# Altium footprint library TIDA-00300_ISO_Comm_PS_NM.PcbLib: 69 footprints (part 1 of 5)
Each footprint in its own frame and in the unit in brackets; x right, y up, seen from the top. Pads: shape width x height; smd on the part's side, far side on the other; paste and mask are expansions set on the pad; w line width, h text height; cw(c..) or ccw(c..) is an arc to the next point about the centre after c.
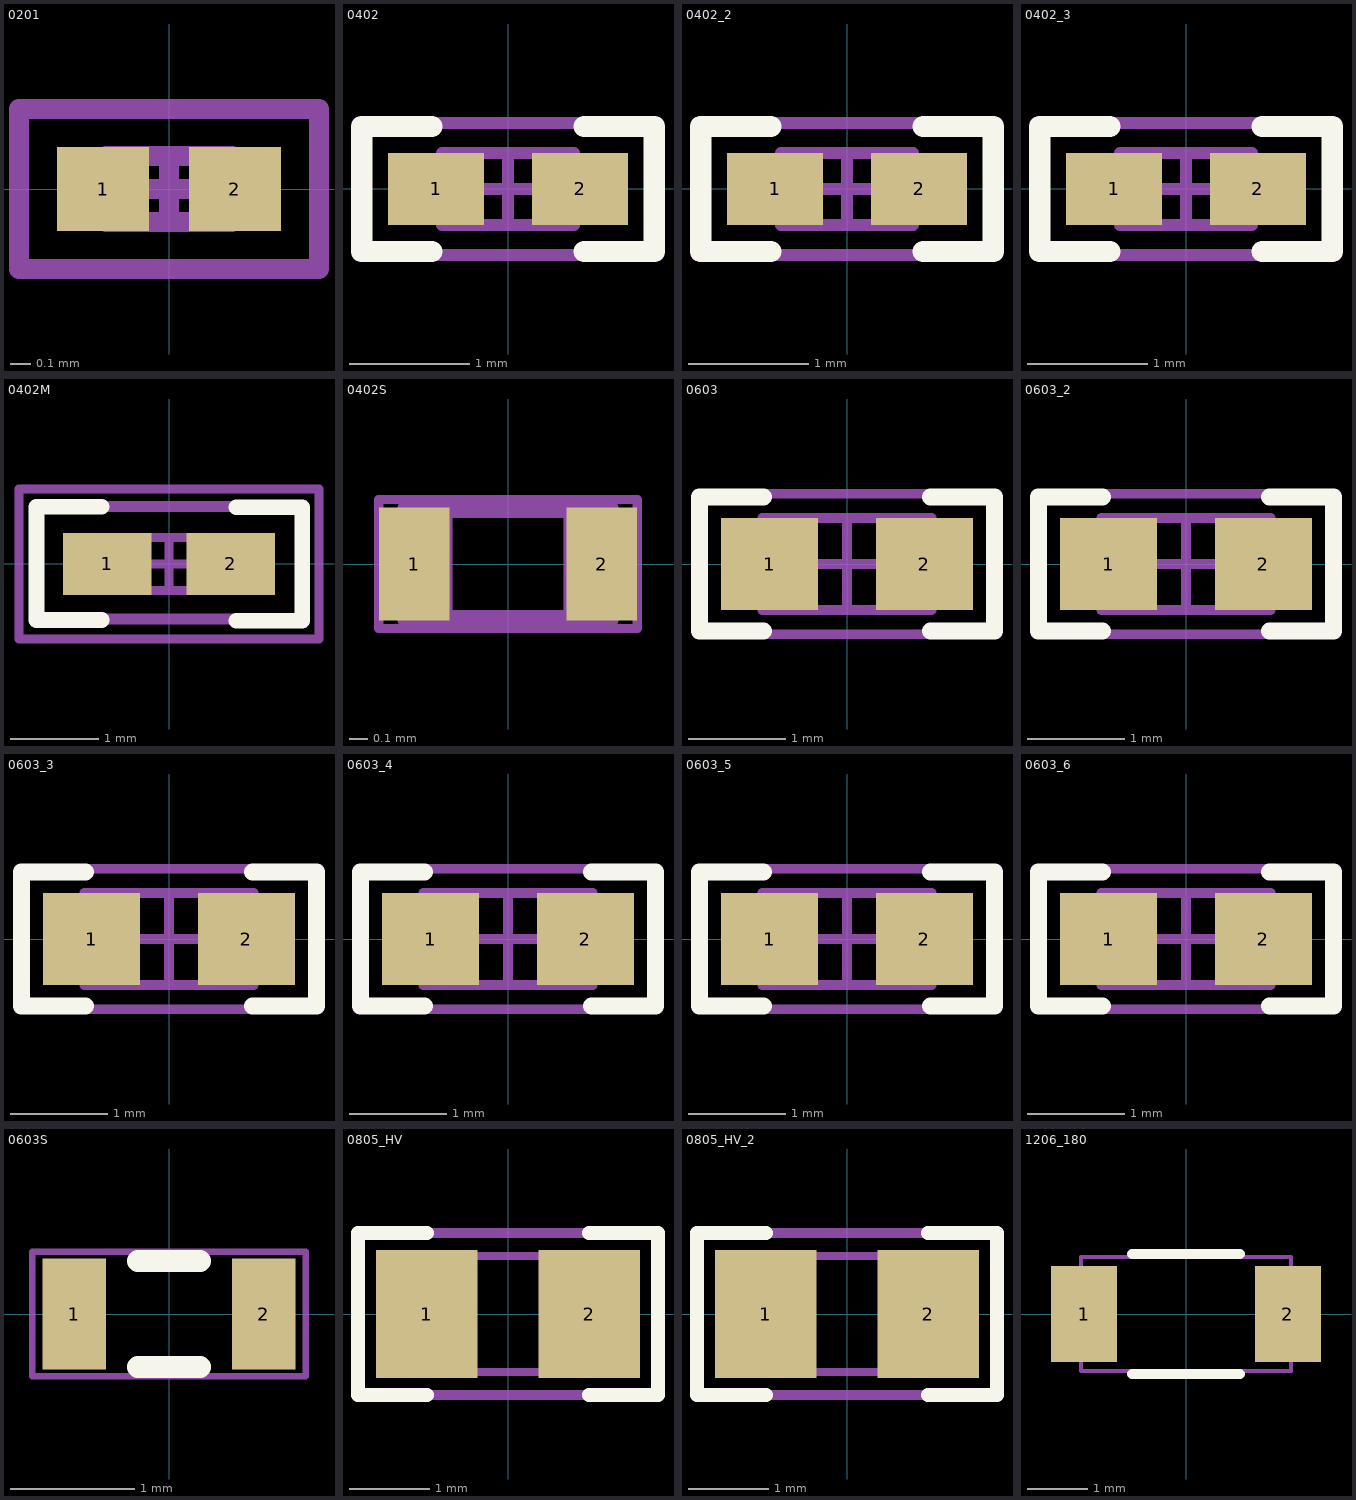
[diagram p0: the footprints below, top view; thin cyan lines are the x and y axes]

## 0201 [mm] "Data from Kemet datasheet CC101_COM dated 7/28/11"
height 0.26
pads (2):
  rect 0.46x0.42 smd mask+0.048: 1(-0.33,0) 2(0.33,0)
Mechanical 5:
  lines w0.1: -0.75,-0.4 0.75,-0.4 0.75,0.4 -0.75,0.4 -0.75,-0.4
  text ".Designator" at -0.654,-1.067 h0.51
Mechanical 13:
  lines w0.1: -0.215,-0.165 -0.215,0.165 ; 0.215,-0.165 0.215,0.165 ; -0.315,-0.165 -0.315,0.165 0.315,0.165 0.315,-0.165 -0.315,-0.165
Mechanical 15:
  lines w0.1: -0.165,0 0.165,0 ; 0,-0.165 0,0.165 ; -0.75,-0.4 -0.75,0.4 0.75,0.4 0.75,-0.4 -0.75,-0.4
3D body: height 0.26, standoff 0, extent -0.314,-0.164 -0.216,0.164
3D body: height 0.26, standoff 0, extent -0.214,-0.164 0.214,0.164
3D body: height 0.26, standoff 0, extent 0.216,-0.164 0.314,0.164

## 0402 [mm] "0402 from SM-752 data"
height 0.6
pads (2):
  rect 0.8x0.6 smd: 1(-0.6,0) 2(0.6,0)
Top Overlay:
  lines w0.178: -0.635,-0.521 -1.219,-0.521 -1.219,0.521 -0.635,0.521 ; 0.635,-0.521 1.219,-0.521 1.219,0.521 0.635,0.521
Mechanical 5:
  lines w0.1: -1.25,-0.55 1.25,-0.55 1.25,0.55 -1.25,0.55 -1.25,-0.55
  text ".Designator" at 0.675,0.165 h0.51
Mechanical 13:
  lines w0.1: -0.35,-0.3 -0.35,0.3 ; 0.35,-0.3 0.35,0.3 ; -0.55,-0.3 -0.55,0.3 0.55,0.3 0.55,-0.3 -0.55,-0.3
Mechanical 15:
  lines w0.1: -0.3,0 0.3,0 ; 0,-0.3 0,0.3 ; -1.25,-0.55 -1.25,0.55 1.25,0.55 1.25,-0.55 -1.25,-0.55
3D body: height 0.6, standoff 0, extent -0.549,-0.299 -0.351,0.299
3D body: height 0.6, standoff 0, extent -0.349,-0.299 0.349,0.299
3D body: height 0.6, standoff 0, extent 0.351,-0.299 0.549,0.299

## 0402_2 [mm]
pads (2):
  rect 0.8x0.6 smd: 1(-0.6,0) 2(0.6,0)
Top Overlay:
  lines w0.178: -0.635,-0.521 -1.219,-0.521 -1.219,0.521 -0.635,0.521 ; 0.635,-0.521 1.219,-0.521 1.219,0.521 0.635,0.521
Mechanical 5:
  lines w0.1: -1.25,-0.55 1.25,-0.55 1.25,0.55 -1.25,0.55 -1.25,-0.55
  text ".Designator" at 0.848,0.205 h0.51
Mechanical 13:
  lines w0.1: -0.35,-0.3 -0.35,0.3 ; 0.35,-0.3 0.35,0.3 ; -0.55,-0.3 -0.55,0.3 0.55,0.3 0.55,-0.3 -0.55,-0.3
Mechanical 15:
  lines w0.1: -0.3,0 0.3,0 ; 0,-0.3 0,0.3 ; -1.25,-0.55 -1.25,0.55 1.25,0.55 1.25,-0.55 -1.25,-0.55
3D body: height 0.6, standoff 0, extent -0.549,-0.299 -0.351,0.299
3D body: height 0.6, standoff 0, extent -0.349,-0.299 0.349,0.299
3D body: height 0.6, standoff 0, extent 0.351,-0.299 0.549,0.299

## 0402_3 [mm]
pads (2):
  rect 0.8x0.6 smd: 1(-0.6,0) 2(0.6,0)
Top Overlay:
  lines w0.178: -0.635,-0.521 -1.219,-0.521 -1.219,0.521 -0.635,0.521 ; 0.635,-0.521 1.219,-0.521 1.219,0.521 0.635,0.521
Mechanical 5:
  lines w0.1: -1.25,-0.55 1.25,-0.55 1.25,0.55 -1.25,0.55 -1.25,-0.55
  text ".Designator" at 0.533,0.278 h0.51
Mechanical 13:
  lines w0.1: -0.35,-0.3 -0.35,0.3 ; 0.35,-0.3 0.35,0.3 ; -0.55,-0.3 -0.55,0.3 0.55,0.3 0.55,-0.3 -0.55,-0.3
Mechanical 15:
  lines w0.1: -0.3,0 0.3,0 ; 0,-0.3 0,0.3 ; -1.25,-0.55 -1.25,0.55 1.25,0.55 1.25,-0.55 -1.25,-0.55
3D body: height 0.6, standoff 0, extent -0.549,-0.299 -0.351,0.299
3D body: height 0.6, standoff 0, extent -0.349,-0.299 0.349,0.299
3D body: height 0.6, standoff 0, extent 0.351,-0.299 0.549,0.299

## 0402M [mm] "0402 from SM-752 data"
height 0.6
pads (2):
  rect 1x0.7 smd: 1(-0.7,0) 2(0.7,0)
Top Overlay:
  lines w0.178: -1.501,-0.635 -0.762,-0.635 ; -1.501,-0.627 -1.501,0.63 ; -1.501,0.65 -0.762,0.65 ; 0.762,-0.643 1.511,-0.643 ; 0.762,0.643 1.511,0.643 ; 1.511,-0.622 1.511,0.635
Mechanical 5:
  lines w0.127: -1.5,-0.625 -1.5,0.65 1.525,0.65 1.525,-0.625 -1.5,-0.625
  text ".Designator" at -1.303,-0.355 h0.51
Mechanical 13:
  lines w0.1: -0.35,-0.3 -0.35,0.3 ; 0.35,-0.3 0.35,0.3 ; -0.55,-0.3 -0.55,0.3 0.55,0.3 0.55,-0.3 -0.55,-0.3
Mechanical 15:
  lines w0.1: -0.3,0 0.3,0 ; 0,-0.3 0,0.3 ; -1.7,-0.85 -1.7,0.85 1.7,0.85 1.7,-0.85 -1.7,-0.85
3D body: height 0.6, standoff 0, extent -0.549,-0.299 -0.351,0.299
3D body: height 0.6, standoff 0, extent -0.349,-0.299 0.349,0.299
3D body: height 0.6, standoff 0, extent 0.351,-0.299 0.549,0.299

## 0402S [mil] "Based on C0402S footprint from PADS legacy"
height 23.62
pads (2):
  rect 15x24 smd: 1(-20,0) 2(20,0)
Mechanical 5:
  lines w1.97: -27.56,-13.78 27.56,-13.78 27.56,13.78 -27.56,13.78 -27.56,-13.78
  text ".Designator" at 26.06,-22 h20
Mechanical 13:
  lines w3.94: -13.78,-11.81 -13.78,11.81 ; 13.78,-11.81 13.78,11.81 ; -21.65,-11.81 -21.65,11.81 21.65,11.81 21.65,-11.81 -21.65,-11.81
3D body: height 23.62, standoff 0, extent -21.63,-11.79 -13.8,11.79
3D body: height 23.62, standoff 0, extent -13.76,-11.79 13.76,11.79
3D body: height 23.62, standoff 0, extent 13.8,-11.79 21.63,11.79

## 0603 [mm] "0603 from SM-752 data"
height 1
pads (2):
  rect 1x0.95 smd: 1(-0.8,0) 2(0.8,0)
Top Overlay:
  lines w0.178: -0.864,-0.691 -1.524,-0.691 -1.524,0.693 -0.864,0.693 ; 0.864,-0.691 1.524,-0.691 1.524,0.693 0.864,0.693
Mechanical 5:
  lines w0.1: -1.55,-0.725 1.55,-0.725 1.55,0.725 -1.55,0.725 -1.55,-0.725
  text ".Designator" at 0.961,0.216 h0.51
Mechanical 13:
  lines w0.1: -0.55,-0.475 -0.55,0.475 ; 0.55,-0.475 0.55,0.475 ; -0.875,-0.475 -0.875,0.475 0.875,0.475 0.875,-0.475 -0.875,-0.475
Mechanical 15:
  lines w0.1: -0.475,0 0.475,0 ; 0,-0.475 0,0.475 ; -1.55,-0.725 -1.55,0.725 1.55,0.725 1.55,-0.725 -1.55,-0.725
3D body: height 1, standoff 0, extent 0.551,-0.474 0.874,0.474
3D body: height 1, standoff 0, extent -0.549,-0.474 0.549,0.474
3D body: height 1, standoff 0, extent -0.874,-0.474 -0.551,0.474

## 0603_2 [mm]
pads (2):
  rect 1x0.95 smd: 1(-0.8,0) 2(0.8,0)
Top Overlay:
  lines w0.178: -0.864,-0.691 -1.524,-0.691 -1.524,0.693 -0.864,0.693 ; 0.864,-0.691 1.524,-0.691 1.524,0.693 0.864,0.693
Mechanical 5:
  lines w0.1: -1.55,-0.725 1.55,-0.725 1.55,0.725 -1.55,0.725 -1.55,-0.725
  text ".Designator" at -0.802,-0.224 h0.51
Mechanical 13:
  lines w0.1: -0.55,-0.475 -0.55,0.475 ; 0.55,-0.475 0.55,0.475 ; -0.875,-0.475 -0.875,0.475 0.875,0.475 0.875,-0.475 -0.875,-0.475
Mechanical 15:
  lines w0.1: -0.475,0 0.475,0 ; 0,-0.475 0,0.475 ; -1.55,-0.725 -1.55,0.725 1.55,0.725 1.55,-0.725 -1.55,-0.725
3D body: height 1, standoff 0, extent 0.551,-0.474 0.874,0.474
3D body: height 1, standoff 0, extent -0.549,-0.474 0.549,0.474
3D body: height 1, standoff 0, extent -0.874,-0.474 -0.551,0.474

## 0603_3 [mm]
pads (2):
  rect 1x0.95 smd: 1(-0.8,0) 2(0.8,0)
Top Overlay:
  lines w0.178: -0.864,-0.691 -1.524,-0.691 -1.524,0.693 -0.864,0.693 ; 0.864,-0.691 1.524,-0.691 1.524,0.693 0.864,0.693
Mechanical 5:
  lines w0.1: -1.55,-0.725 1.55,-0.725 1.55,0.725 -1.55,0.725 -1.55,-0.725
  text ".Designator" at -0.859,-0.239 h0.51
Mechanical 13:
  lines w0.1: -0.55,-0.475 -0.55,0.475 ; 0.55,-0.475 0.55,0.475 ; -0.875,-0.475 -0.875,0.475 0.875,0.475 0.875,-0.475 -0.875,-0.475
Mechanical 15:
  lines w0.1: -0.475,0 0.475,0 ; 0,-0.475 0,0.475 ; -1.55,-0.725 -1.55,0.725 1.55,0.725 1.55,-0.725 -1.55,-0.725
3D body: height 1, standoff 0, extent 0.551,-0.474 0.874,0.474
3D body: height 1, standoff 0, extent -0.549,-0.474 0.549,0.474
3D body: height 1, standoff 0, extent -0.874,-0.474 -0.551,0.474

## 0603_4 [mm]
pads (2):
  rect 1x0.95 smd: 1(-0.8,0) 2(0.8,0)
Top Overlay:
  lines w0.178: -0.864,-0.691 -1.524,-0.691 -1.524,0.693 -0.864,0.693 ; 0.864,-0.691 1.524,-0.691 1.524,0.693 0.864,0.693
Mechanical 5:
  lines w0.1: -1.55,-0.725 -1.55,0.725 1.55,0.725 1.55,-0.725 -1.55,-0.725
  text ".Designator" at 0.94,0.254 h0.51
Mechanical 13:
  lines w0.1: -0.55,-0.475 -0.55,0.475 ; 0.55,-0.475 0.55,0.475 ; -0.875,-0.475 0.875,-0.475 0.875,0.475 -0.875,0.475 -0.875,-0.475
Mechanical 15:
  lines w0.1: -0.475,0 0.475,0 ; 0,-0.475 0,0.475 ; -1.55,-0.725 1.55,-0.725 1.55,0.725 -1.55,0.725 -1.55,-0.725
3D body: height 1, standoff 0, extent -0.874,-0.474 -0.551,0.474
3D body: height 1, standoff 0, extent -0.549,-0.474 0.549,0.474
3D body: height 1, standoff 0, extent 0.551,-0.474 0.874,0.474

## 0603_5 [mm]
pads (2):
  rect 1x0.95 smd: 1(-0.8,0) 2(0.8,0)
Top Overlay:
  lines w0.178: -0.864,-0.691 -1.524,-0.691 -1.524,0.693 -0.864,0.693 ; 0.864,-0.691 1.524,-0.691 1.524,0.693 0.864,0.693
Mechanical 5:
  lines w0.1: -1.55,-0.725 1.55,-0.725 1.55,0.725 -1.55,0.725 -1.55,-0.725
  text ".Designator" at 0.533,0.254 h0.51
Mechanical 13:
  lines w0.1: -0.55,-0.475 -0.55,0.475 ; 0.55,-0.475 0.55,0.475 ; -0.875,-0.475 -0.875,0.475 0.875,0.475 0.875,-0.475 -0.875,-0.475
Mechanical 15:
  lines w0.1: -0.475,0 0.475,0 ; 0,-0.475 0,0.475 ; -1.55,-0.725 -1.55,0.725 1.55,0.725 1.55,-0.725 -1.55,-0.725
3D body: height 1, standoff 0, extent 0.551,-0.474 0.874,0.474
3D body: height 1, standoff 0, extent -0.549,-0.474 0.549,0.474
3D body: height 1, standoff 0, extent -0.874,-0.474 -0.551,0.474

## 0603_6 [mm]
pads (2):
  rect 1x0.95 smd: 1(-0.8,0) 2(0.8,0)
Top Overlay:
  lines w0.178: -0.864,-0.691 -1.524,-0.691 -1.524,0.693 -0.864,0.693 ; 0.864,-0.691 1.524,-0.691 1.524,0.693 0.864,0.693
Mechanical 5:
  lines w0.1: -1.55,-0.725 1.55,-0.725 1.55,0.725 -1.55,0.725 -1.55,-0.725
  text ".Designator" at -0.584,-0.254 h0.51
Mechanical 13:
  lines w0.1: -0.55,-0.475 -0.55,0.475 ; 0.55,-0.475 0.55,0.475 ; -0.875,-0.475 -0.875,0.475 0.875,0.475 0.875,-0.475 -0.875,-0.475
Mechanical 15:
  lines w0.1: -0.475,0 0.475,0 ; 0,-0.475 0,0.475 ; -1.55,-0.725 -1.55,0.725 1.55,0.725 1.55,-0.725 -1.55,-0.725
3D body: height 1, standoff 0, extent 0.551,-0.474 0.874,0.474
3D body: height 1, standoff 0, extent -0.549,-0.474 0.549,0.474
3D body: height 1, standoff 0, extent -0.874,-0.474 -0.551,0.474

## 0603S [mil]
height 39.37
pads (2):
  rect 20x35 smd: 1(-30,0) 2(30,0)
Top Overlay:
  lines w7: -9.84,-16.73 9.84,-16.73 ; -9.84,16.73 9.84,16.73
Mechanical 5:
  lines w1.97: -43.31,-19.68 43.31,-19.68 43.31,19.68 -43.31,19.68 -43.31,-19.68
  text ".Designator" at -32.48,-8.86 h20
3D body: height 39.37, standoff 0, extent -34.43,-18.68 -21.67,18.68
3D body: height 39.37, standoff 0, extent -21.63,-18.68 21.63,18.68
3D body: height 39.37, standoff 0, extent 21.67,-18.68 34.43,18.68

## 0805_HV [mil] "0805 with 30mil clearance between pads"
height 57.09
pads (2):
  rect 50x63 smd: 1(-40,0) 2(40,0)
Top Overlay:
  lines w7: -40,-40 -74,-40 -74,0 -74,40 -40,40 ; 40,-40 74,-40 74,0 74,40 40,40
Mechanical 5:
  lines w5: -74,-40 74,-40 74,40 -74,40 -74,-40
  text ".Designator" at 29.58,8.82 h20
Mechanical 13:
  lines w3.94: -25.59,-28.54 -25.59,28.54 ; 25.59,-28.54 25.59,28.54 ; -43.31,-28.54 43.31,-28.54 43.31,28.54 -43.31,28.54 -43.31,-28.54
3D body: height 57.09, standoff 0, extent -43.29,-28.52 -25.61,28.52
3D body: height 57.09, standoff 0, extent -25.57,-28.52 25.57,28.52
3D body: height 57.09, standoff 0, extent 25.61,-28.52 43.29,28.52

## 0805_HV_2 [mil]
pads (2):
  rect 50x63 smd: 1(-40,0) 2(40,0)
Top Overlay:
  lines w7: -40,-40 -74,-40 -74,0 -74,40 -40,40 ; 40,-40 74,-40 74,0 74,40 40,40
Mechanical 5:
  lines w5: -74,-40 74,-40 74,40 -74,40 -74,-40
  text ".Designator" at 27,9 h20
Mechanical 13:
  lines w3.94: -25.59,-28.54 -25.59,28.54 ; 25.59,-28.54 25.59,28.54 ; -43.31,-28.54 43.31,-28.54 43.31,28.54 -43.31,28.54 -43.31,-28.54
3D body: height 57.09, standoff 0, extent -43.29,-28.52 -25.61,28.52
3D body: height 57.09, standoff 0, extent -25.57,-28.52 25.57,28.52
3D body: height 57.09, standoff 0, extent 25.61,-28.52 43.29,28.52

## 1206_180 [mm] "1206_180"
height 1.8
pads (2):
  rect 1.1x1.6 smd: 1(-1.7,0) 2(1.7,0)
Top Overlay:
  lines w0.17: -0.9,-1 0.9,-1 ; -0.9,1 0.9,1
Mechanical 5:
  lines w0.07: -1.75,-0.95 -1.75,0.95 1.75,0.95 1.75,-0.95 -1.75,-0.95
  text ".Designator" at 0.955,0.173 h0.51
3D body: height 1.8, standoff 0, extent 1.301,-0.949 1.749,0.949
3D body: height 1.8, standoff 0, extent -1.299,-0.949 1.299,0.949
3D body: height 1.8, standoff 0, extent -1.749,-0.949 -1.301,0.949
